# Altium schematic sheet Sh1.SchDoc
size A4; SheetNumber: 1; SheetTotal: 1
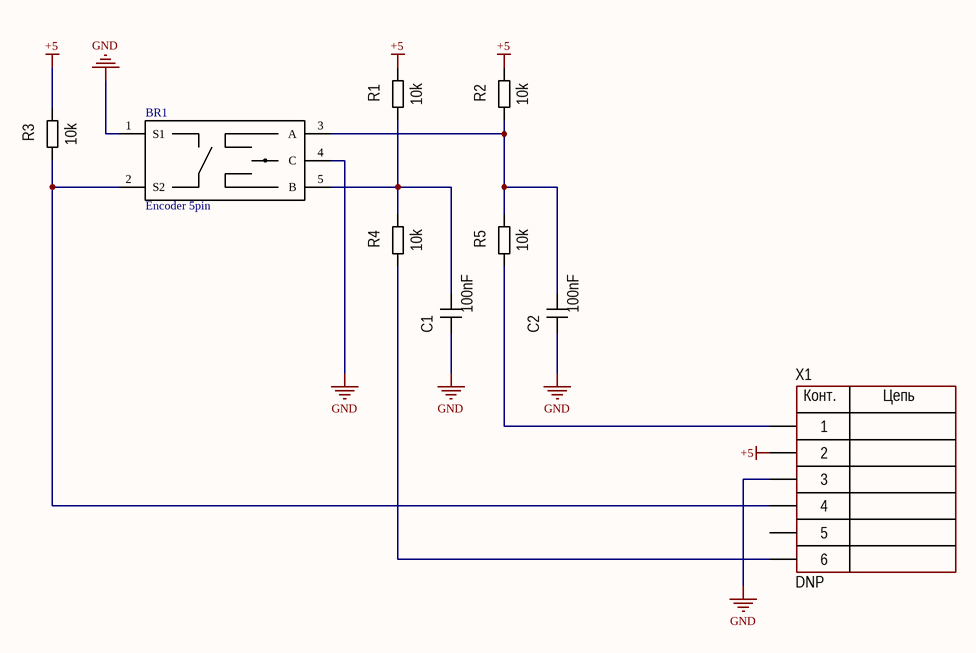
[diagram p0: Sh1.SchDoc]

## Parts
BR1  Encoder 5pin  [Enc-5pin]
C1  100nF  [CH0603C]
C2  100nF  [CH0603C]
R1  10k  [CH0603R]
R2  10k  [CH0603R]
R3  10k  [CH0603R]
R4  10k  [CH0603R]
R5  10k  [CH0603R]
X1  DNP  [CON: PBD-6]

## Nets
+5: R1.2 R2.2 R3.2 X1.2
GND: BR1.1(S1) BR1.4(C) C1.1 C2.1 X1.3
NetBR1_2: BR1.2(S2) R3.1 X1.4
NetBR1_3: BR1.3(A) C2.2 R2.1 R5.2
NetBR1_5: BR1.5(B) C1.2 R1.1 R4.2
NetR4_1: R4.1 X1.6
NetR5_1: R5.1 X1.1

Not connected (* = marked no-connect by the designer): X1 5

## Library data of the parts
BR1 = Encoder 5pin: Model: EC-11
C1 C2 = Capacitor: Model: 06035C104JAT2A
R1-R5 = Resistor: Model: CR0603-FX-1002ELF
X1 = 6-Connector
